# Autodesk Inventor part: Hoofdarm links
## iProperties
Created: 2007-06
Part Number: Hoofdarm links
Material: Steel
Document SubType Name: Modeling
Designer: Phil Trethewie
Author: Phil Trethewie
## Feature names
1. Extrusion3
2. Derived Body1 [Tagging]
